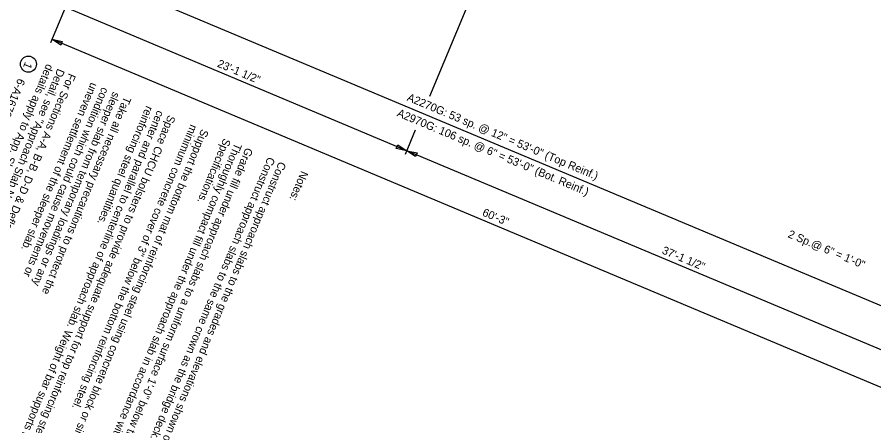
# Model space of a CAD drawing. Extents: x 1968564 to 1968701, y 796599 to 796766.
# Drawn here: x 1968596.1 to 1968649.6, y 796643.8 to 796669.3 of the extents above; entities that cross this region are included whole.
import ezdxf

# ---------------------------------------------------------------- set-up
doc = ezdxf.new("R2010")
doc.units = 0
doc.layers.add('BR_AUTO DIMENSION', color=7, linetype='Continuous')
doc.layers.add('BR_TEXT', color=7, linetype='Continuous')

msp = doc.modelspace()

# ---------------------------------------------------------------- linework, layer by layer
at = {"layer": 'BR_AUTO DIMENSION'}
for p, q in [((1968628.075, 796679.15), (1968621.849, 796664.307)), ((1968599.902, 796671.768), (1968598.173, 796667.646)), ((1968654.146, 796649.526), (1968601.582, 796671.573)), ((1968620.43, 796660.923), (1968599.105, 796669.867)), ((1968653.831, 796644.573), (1968598.27, 796667.876)), ((1968620.964, 796662.195), (1968620.333, 796660.692)), ((1968654.666, 796646.564), (1968620.43, 796660.923))]:
    msp.add_line(p, q, dxfattribs=at)
for points in [[(1968598.821, 796667.509), (1968598.27, 796667.876), (1968598.917, 796667.74)], [(1968619.879, 796661.289), (1968620.43, 796660.923), (1968619.782, 796661.059)], [(1968620.981, 796660.556), (1968620.43, 796660.923), (1968621.078, 796660.787)]]:
    msp.add_lwpolyline(points, close=True, dxfattribs=at)
msp.add_circle((1968596.801, 796666.321), 0.502, dxfattribs=at)

# ---------------------------------------------------------------- texts
for s, height, rotation, p in [('1', 0.5, 247.246, (1968596.603, 796666.495)), ('23\'-1 1/2"', 0.5, 337.246, (1968608.554, 796666.175)), ('A2270G: 53 sp. @ 12" = 53\'-0" (Top Reinf.)', 0.5, 337.246, (1968620.409, 796664.065)), ('A2970G: 106 sp. @ 6" = 53\'-0" (Bot. Reinf.)', 0.5, 337.246, (1968619.785, 796663.091)), ('60\'-3"', 0.5, 337.246, (1968625.113, 796656.889)), ('2 Sp.@ 6" = 1\'-0"', 0.49995, 337.246, (1968644.202, 796655.536)), ('37\'-1 1/2"', 0.5, 337.246, (1968636.335, 796654.523))]:
    msp.add_text(s, height=height, rotation=rotation, dxfattribs=at).set_placement(p)
at = {"layer": 'BR_TEXT'}
for s, height, p in [('Detail, see "Approach Slab No. 3" sheet.  These ', 0.49995, (1968598.628, 796666.08)), ('details apply to App. Slab No. 2 also.', 0.49995, (1968597.936, 796666.37)), ('6-A1673G @ 12" placed between A2270G bars ', 0.49995, (1968596.16, 796665.469)), ('For Sections A-A, B-B, D-D & Deflection Joint ', 0.49995, (1968599.32, 796665.79)), ('uneven settlement of the sleeper slab.  ', 0.49995, (1968600.703, 796665.21)), ('condition which could cause movements or ', 0.49995, (1968601.394, 796664.92)), ('sleeper slab from temporary loadings or any ', 0.49995, (1968602.086, 796664.63)), ('Take all necessary precautions to protect the ', 0.49995, (1968602.777, 796664.34)), ('reinforcing steel quantities.', 0.49995, (1968604.161, 796663.76)), ('center and parallel to centerline of approach slab. Weight of bar supports is not included in the ', 0.49995, (1968604.852, 796663.47)), ('Space CHCU bolsters to provide adequate support for top reinforcing steel, approximately 2\'-6" on ', 0.49995, (1968605.544, 796663.18)), ('Support the bottom mat of reinforcing steel using concrete block or similar material. Provide a ', 0.49995, (1968607.618, 796662.31)), ('minimum concrete cover of 3" below the bottom reinforcing steel.', 0.49995, (1968606.927, 796662.6)), ('Specifications.', 0.49995, (1968609.001, 796661.73)), ('Thoroughly compact fill under the approach slab in accordance with Section 208 of the Standard ', 0.49995, (1968609.693, 796661.44)), ('Grade fill under approach slabs to a uniform surface 1\'-0" below the finished surface of roadway. ', 0.49995, (1968610.385, 796661.15)), ('Construct approach slabs to the grades and elevations shown on the Bridge Plan and Profile drawing. ', 0.49995, (1968612.459, 796660.279)), ('Construct approach slabs to the same crown as the bridge deck.', 0.49995, (1968611.768, 796660.569)), ('Notes:', 0.4999, (1968613.842, 796659.699))]:
    msp.add_text(s, height=height, rotation=247.246, dxfattribs=at).set_placement(p)

doc.saveas('drawing.dxf')
